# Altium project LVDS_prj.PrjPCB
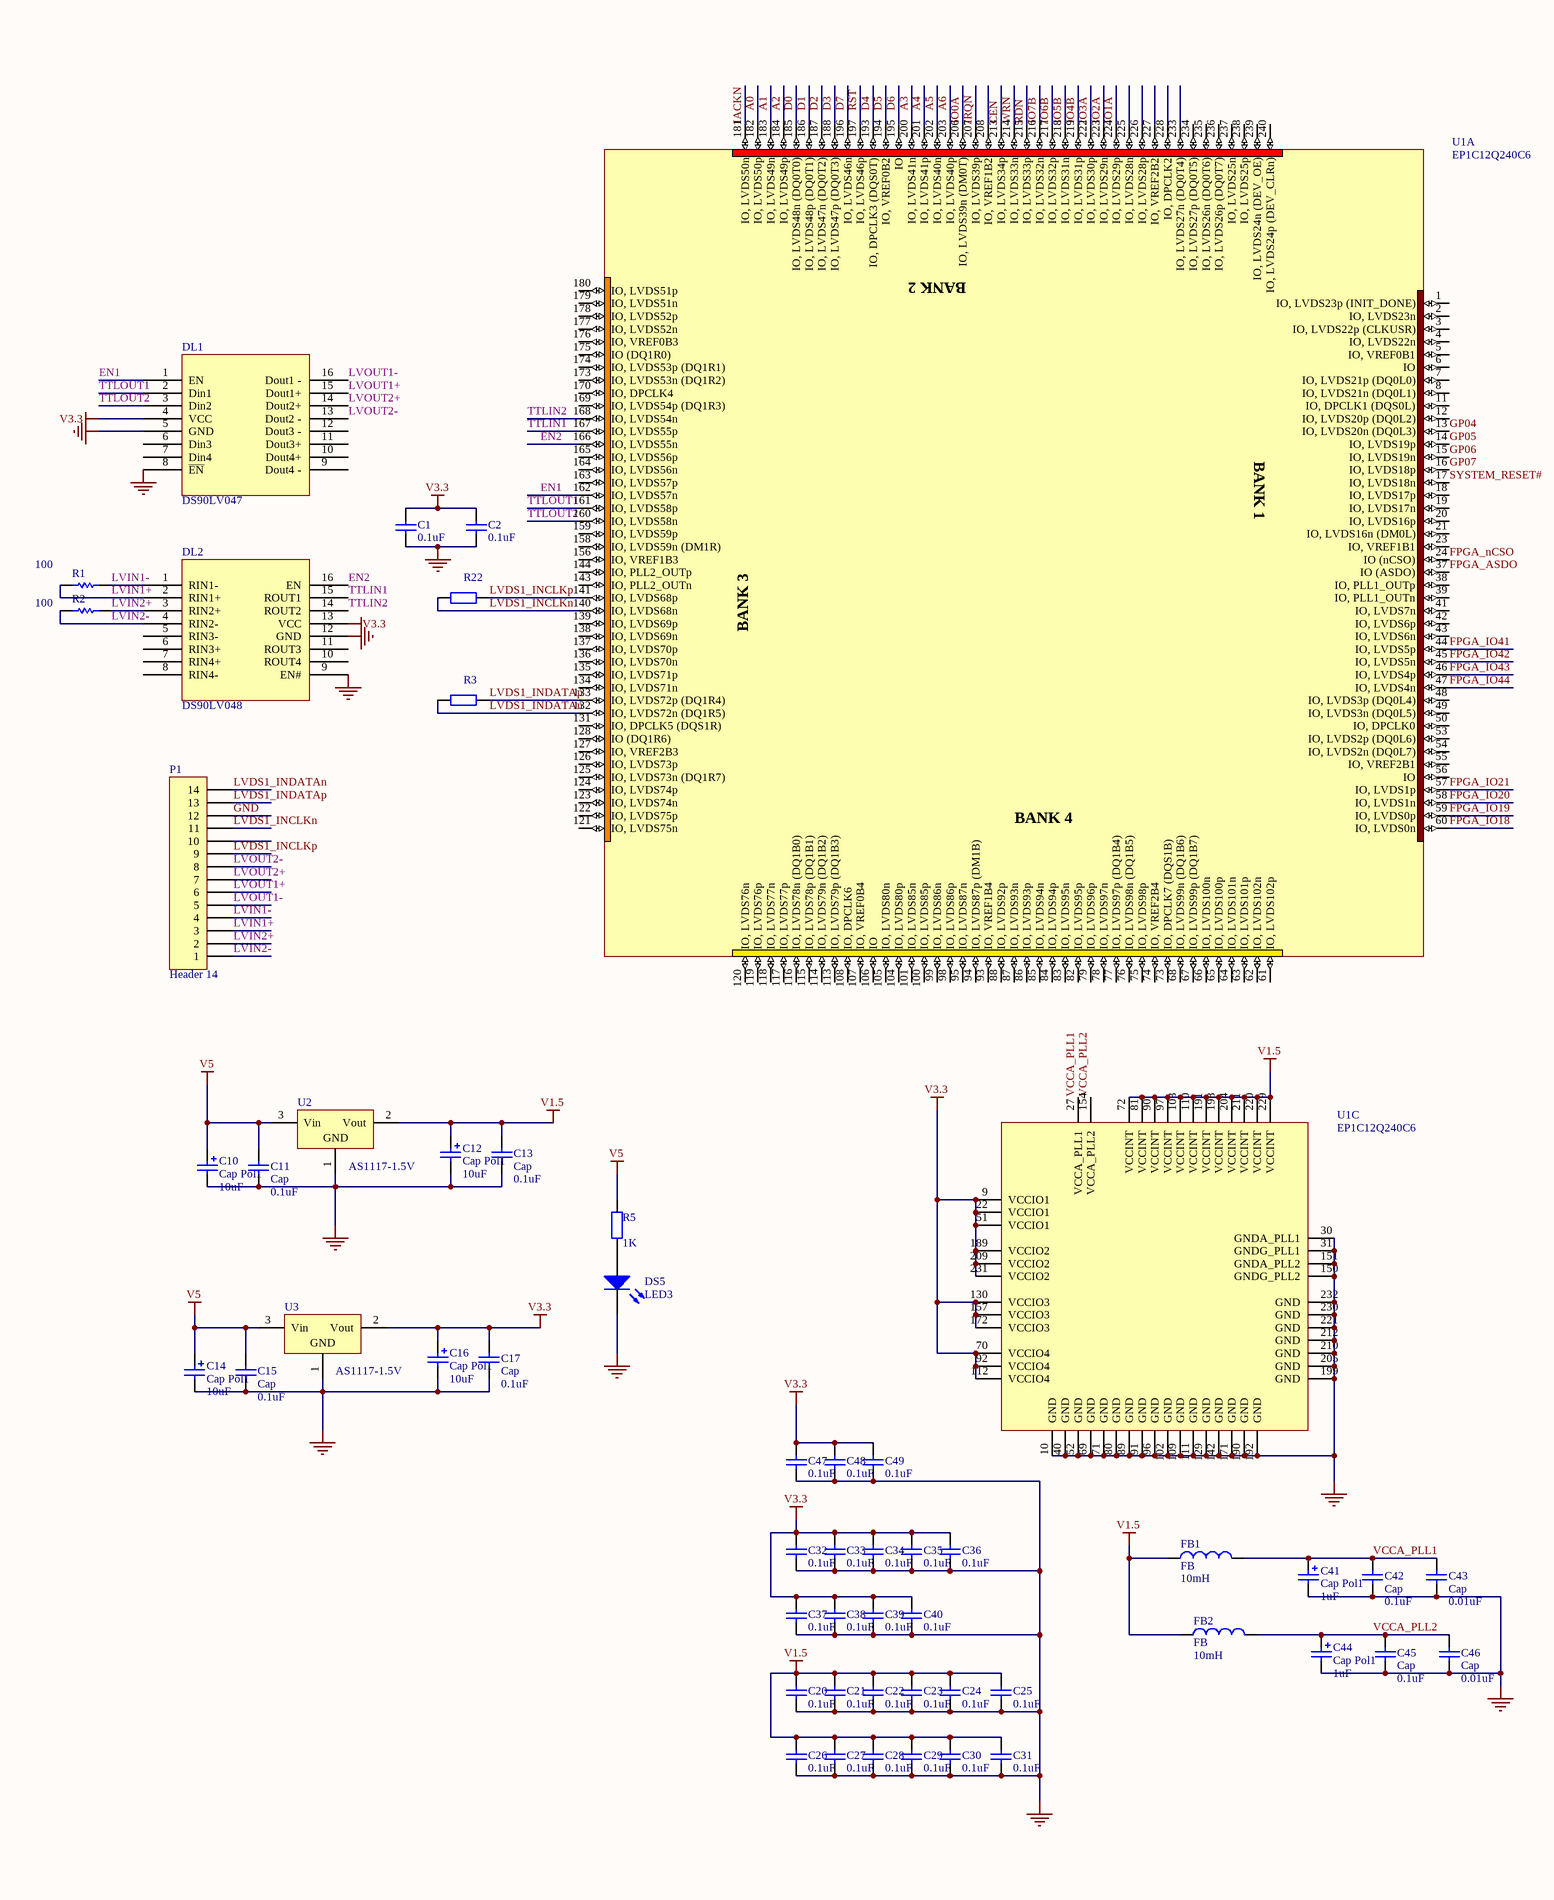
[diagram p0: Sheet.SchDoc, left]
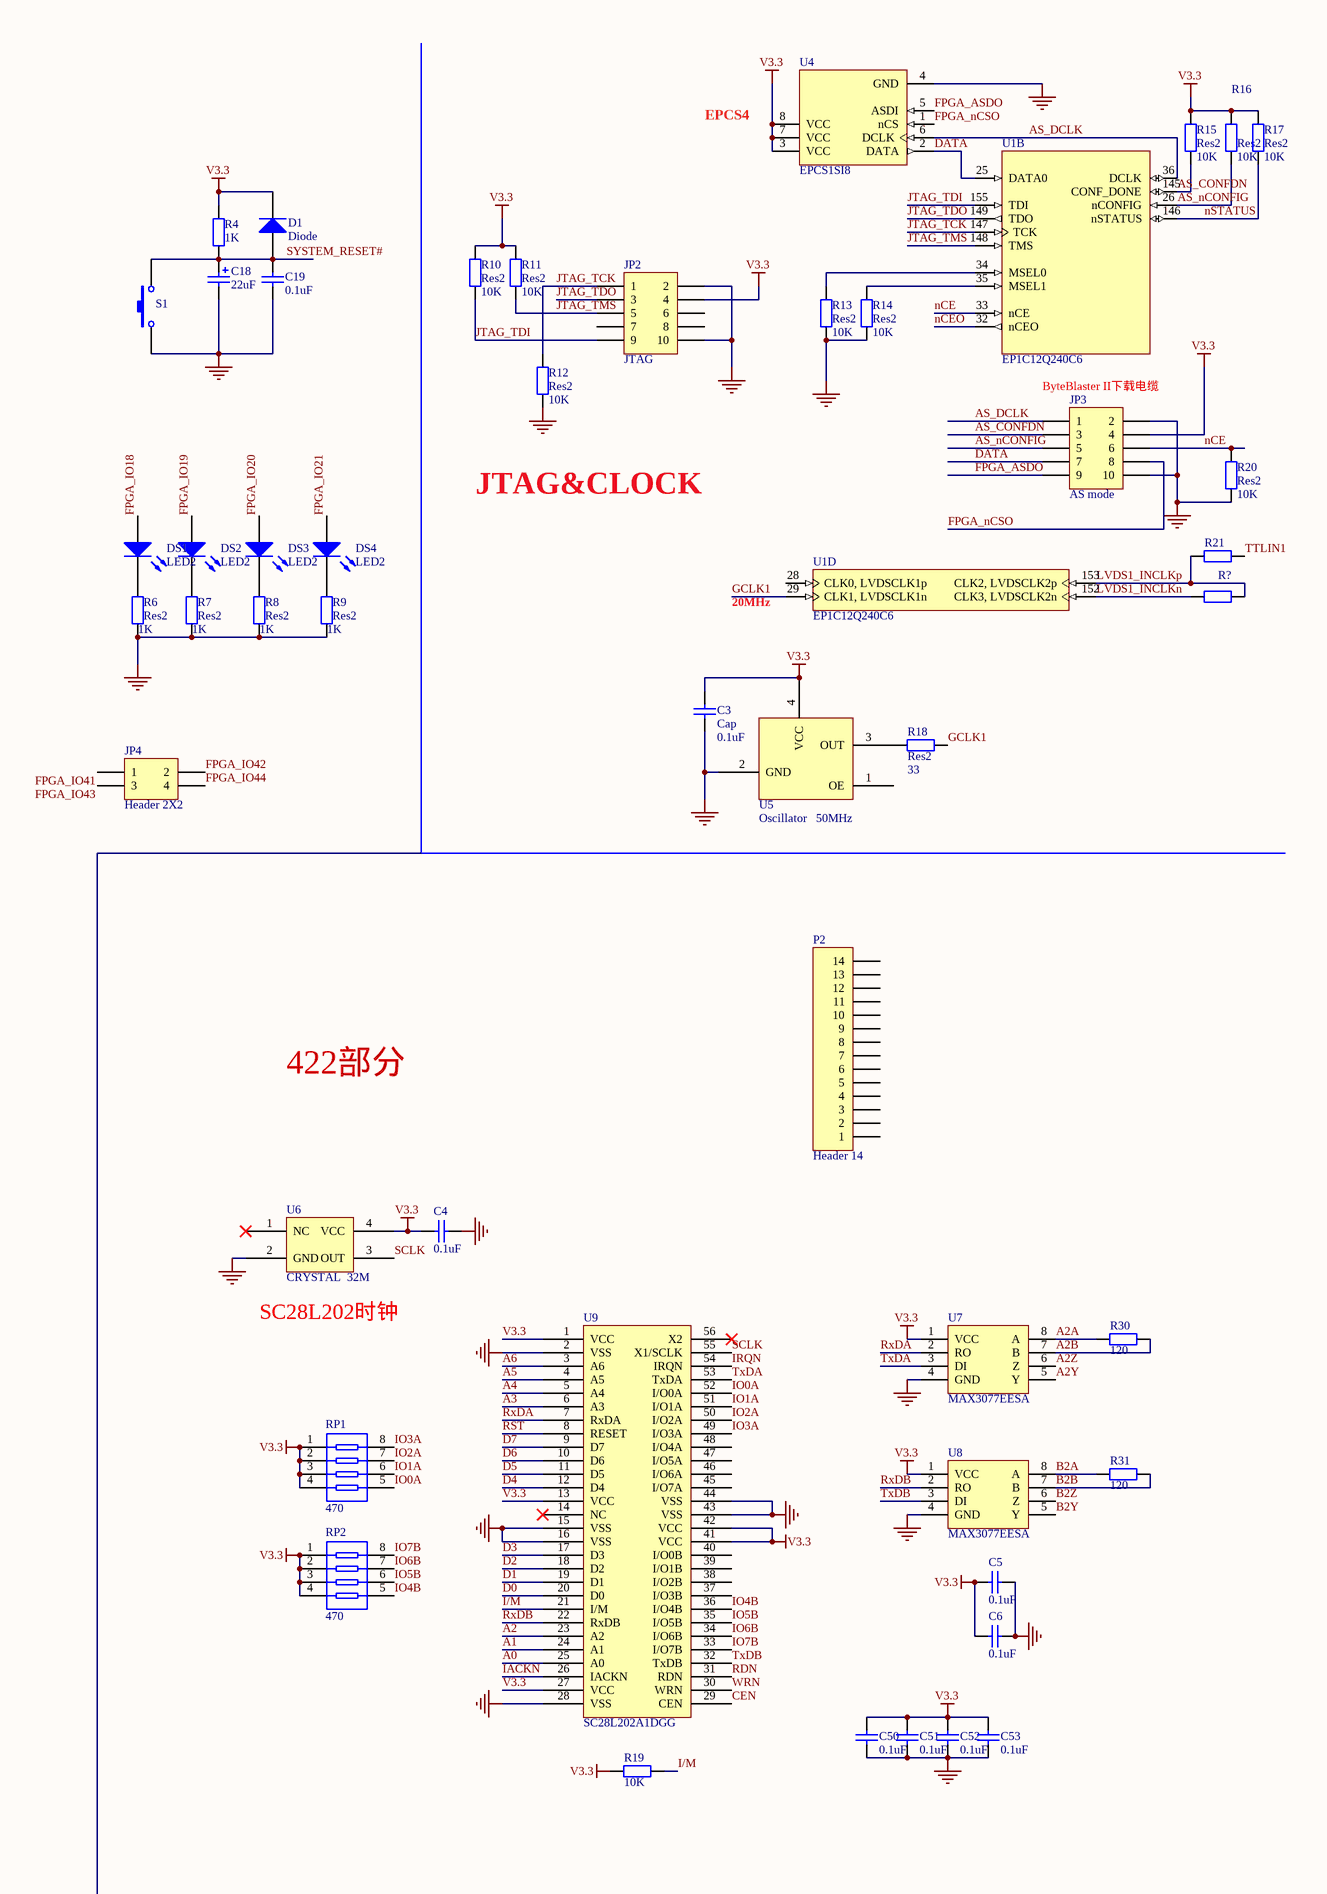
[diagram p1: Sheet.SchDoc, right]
1 sheet, 102 parts. Net scope: global (net labels, ports and power ports of the same name join across sheets).
Board files: PCB2_back_new.PcbDoc, LVDS_RS422.PcbDoc

## Sheet Sheet.SchDoc
size A2

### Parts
(Parts that share a designator on the sheet are numbered #1, #2 ... from top to bottom, then left to right.)
C1  0.1uF  [C1608-0603]
C2  0.1uF  [C1608-0603]
C3  Cap  value 0.1uF  [C1608-0603]
C4  0.1uF  [C1608-0603]
C5  0.1uF  [C1608-0603]
C6  0.1uF  [C1608-0603]
C10  Cap Pol1  value 10uF  [CC3216-1206]
C11  Cap  value 0.1uF  [C1608-0603]
C12  Cap Pol1  value 10uF  [CC3216-1206]
C13  Cap  value 0.1uF  [C1608-0603]
C14  Cap Pol1  value 10uF  [CC3216-1206]
C15  Cap  value 0.1uF  [C1608-0603]
C16  Cap Pol1  value 10uF  [CC3216-1206]
C17  Cap  value 0.1uF  [C1608-0603]
C18  22uF  [CC3216-1206]
C19  0.1uF  [C1608-0603]
C20  value 0.1uF  [0603]  (hidden comment: Cap)
C21  value 0.1uF  [0603]  (hidden comment: Cap)
C22  value 0.1uF  [0603]  (hidden comment: Cap)
C23  value 0.1uF  [0603]  (hidden comment: Cap)
C24  value 0.1uF  [0603]  (hidden comment: Cap)
C25  value 0.1uF  [0603]  (hidden comment: Cap)
C26  value 0.1uF  [0603]  (hidden comment: Cap)
C27  value 0.1uF  [0603]  (hidden comment: Cap)
C28  value 0.1uF  [0603]  (hidden comment: Cap)
C29  value 0.1uF  [0603]  (hidden comment: Cap)
C30  value 0.1uF  [0603]  (hidden comment: Cap)
C31  value 0.1uF  [0603]  (hidden comment: Cap)
C32  value 0.1uF  [0603]  (hidden comment: Cap)
C33  value 0.1uF  [0603]  (hidden comment: Cap)
C34  value 0.1uF  [0603]  (hidden comment: Cap)
C35  value 0.1uF  [0603]  (hidden comment: Cap)
C36  value 0.1uF  [0603]  (hidden comment: Cap)
C37  value 0.1uF  [0603]  (hidden comment: Cap)
C38  value 0.1uF  [0603]  (hidden comment: Cap)
C39  value 0.1uF  [0603]  (hidden comment: Cap)
C40  value 0.1uF  [0603]  (hidden comment: Cap)
C41  Cap Pol1  value 1uF  [C1608-0603]
C42  Cap  value 0.1uF  [C1608-0603]
C43  Cap  value 0.01uF  [C1608-0603]
C44  Cap Pol1  value 1uF  [C1608-0603]
C45  Cap  value 0.1uF  [C1608-0603]
C46  Cap  value 0.01uF  [C1608-0603]
C47  value 0.1uF  [0603]  (hidden comment: Cap)
C48  value 0.1uF  [0603]  (hidden comment: Cap)
C49  value 0.1uF  [0603]  (hidden comment: Cap)
C50  0.1uF  [C1608-0603]
C51  0.1uF  [C1608-0603]
C52  0.1uF  [C1608-0603]
C53  0.1uF  [C1608-0603]
D1  Diode  [SMD _LED]
DL1  DS90LV047  [SO-16]
DL2  DS90LV048  [SO-16]
DS1  LED2  [SMD _LED]
DS2  LED2  [SMD _LED]
DS3  LED2  [SMD _LED]
DS4  LED2  [SMD _LED]
DS5  LED3  [SMD _LED]
FB1  FB  value 10mH  [C1608-0603]
FB2  FB  value 10mH  [C1608-0603]
JP2  JTAG  [HDR2X5]
JP3  AS mode  [HDR2X5]
JP4  Header 2X2  [HDR2X2]
P1  Header 14  [CHAMP1.27-2H14A]
P2  Header 14  [CHAMP1.27-2H14A]
R1  value 100  [CR1608-0603]
R2  value 100  [CR1608-0603]
R3  Res2  [C1608-0603]  (value not drawn)
R4  1K  [CR1608-0603]
R5  value 1K  [CR1608-0603]  (hidden comment: Res2)
R6  Res2  value 1K  [C1608-0603]
R7  Res2  value 1K  [C1608-0603]
R8  Res2  value 1K  [C1608-0603]
R9  Res2  value 1K  [C1608-0603]
R10  Res2  value 10K  [C1608-0603]
R11  Res2  value 10K  [C1608-0603]
R12  Res2  value 10K  [C1608-0603]
R13  Res2  value 10K  [C1608-0603]
R14  Res2  value 10K  [C1608-0603]
R15  Res2  value 10K  [C1608-0603]
R16  Res2  value 10K  [C1608-0603]
R17  Res2  value 10K  [C1608-0603]
R18  Res2  value 33  [C1608-0603]
R19  10K  [CR1608-0603]
R20  Res2  value 10K  [C1608-0603]
R21  Res2  [C1608-0603]  (value not drawn)
R22#1  Res2  [C1608-0603]  (value not drawn)
R22#2  Res2  [C1608-0603]  (value not drawn)
R30  120  [CR1608-0603]
R31  120  [CR1608-0603]
RP1  470  [RP8]
RP2  470  [RP8]
S1  SW  [BUTTON]  (value not drawn)
U1  EP1C12Q240C6  [PQFP240]  (parts A,B,C,D of 4)
U2  AS1117-1.5V  [LM1117]
U3  AS1117-1.5V  [LM1117]
U4  EPCS1SI8  [SOIC8]
U5  Oscillator   50MHz  [OSC]
U6  CRYSTAL  32M  [OSC]
U7  MAX3077EESA  [SO-G8]
U8  MAX3077EESA  [SO-G8]
U9  SC28L202A1DGG  [TSSOP56]

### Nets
GND: C1.2 C2.2 C3.1 C4.2 C5.2 C6.2 C10.2 C11.1 C12.2 C13.1 C14.2 C15.1 C16.2 C17.1 C18.2 C19.1 C20.2 C21.2 C22.2 C23.2 C24.2 C25.2 C26.2 C27.2 C28.2 C29.2 C30.2 C31.2 C32.2 C33.2 C34.2 C35.2 C36.2 C37.2 C38.2 C39.2 C40.2 C41.2 C42.1 C43.1 C44.2 C45.1 C46.1 C47.2 C48.2 C49.2 C50.1 C51.1 C52.1 C53.1 DL1.5(GND) DL1.8(~{EN}) DL2.9(EN#) DL2.12(GND) DS5.2(K) JP2.2 JP2.10 JP3.2 JP3.10 P1.12 R6.2 R7.2 R8.2 R9.2 R12.1 R13.1 R14.1 R20.1 S1.1 U1.10(GND) U1.30(GNDA_PLL1) U1.31(GNDG_PLL1) U1.40(GND) U1.52(GND) U1.69(GND) U1.71(GND) U1.80(GND) U1.89(GND) U1.91(GND) U1.96(GND) U1.102(GND) U1.109(GND) U1.111(GND) U1.129(GND) U1.142(GND) U1.150(GNDG_PLL2) U1.151(GNDA_PLL2) U1.171(GND) U1.190(GND) U1.192(GND) U1.199(GND) U1.205(GND) U1.210(GND) U1.212(GND) U1.221(GND) U1.230(GND) U1.232(GND) U2.1(GND) U3.1(GND) U4.4(GND) U5.2(GND) U6.2(GND) U7.4(GND) U8.4(GND) U9.2(VSS) U9.15(VSS) U9.16(VSS) U9.28(VSS) U9.43(VSS) U9.44(VSS)
V1.5: C12.1 C13.2 C20.1 C21.1 C22.1 C23.1 C24.1 C25.1 C26.1 C27.1 C28.1 C29.1 C30.1 C31.1 FB1.1 FB2.1 U1.72(VCCINT) U1.81(VCCINT) U1.90(VCCINT) U1.97(VCCINT) U1.103(VCCINT) U1.110(VCCINT) U1.191(VCCINT) U1.198(VCCINT) U1.204(VCCINT) U1.211(VCCINT) U1.220(VCCINT) U1.229(VCCINT) U2.2(Vout)
V3.3: C1.1 C2.1 C3.2 C4.1 C5.1 C6.1 C16.1 C17.2 C32.1 C33.1 C34.1 C35.1 C36.1 C37.1 C38.1 C39.1 C40.1 C47.1 C48.1 C49.1 C50.2 C51.2 C52.2 C53.2 D1.2(K) DL1.4(VCC) DL2.13(VCC) JP2.4 JP3.4 R4.2 R10.2 R11.2 R15.2 R16.2 R17.2 R19.1 RP1.1 RP1.2 RP1.3 RP1.4 RP2.1 RP2.2 RP2.3 RP2.4 U1.9(VCCIO1) U1.22(VCCIO1) U1.51(VCCIO1) U1.70(VCCIO4) U1.92(VCCIO4) U1.112(VCCIO4) U1.130(VCCIO3) U1.157(VCCIO3) U1.172(VCCIO3) U1.189(VCCIO2) U1.209(VCCIO2) U1.231(VCCIO2) U3.2(Vout) U4.3(VCC) U4.7(VCC) U4.8(VCC) U5.4(VCC) U6.4(VCC) U7.1(VCC) U8.1(VCC) U9.1(VCC) U9.13(VCC) U9.27(VCC) U9.41(VCC) U9.42(VCC)
V5: C10.1 C11.2 C14.1 C15.2 R5.2 U2.3(Vin) U3.3(Vin)
A0: U1.182(IO,_LVDS50p) U9.25(A0)
A1: U1.183(IO,_LVDS49n) U9.24(A1)
A2: U1.184(IO,_LVDS49p) U9.23(A2)
A2A: R30.1 U7.8(A)
A2B: R30.2 U7.7(B)
A2Y: U7.5(Y)
A2Z: U7.6(Z)
A3: U1.200(IO,_LVDS41n) U9.6(A3)
A4: U1.201(IO,_LVDS41p) U9.5(A4)
A5: U1.202(IO,_LVDS40n) U9.4(A5)
A6: U1.203(IO,_LVDS40p) U9.3(A6)
AS_CONFDN: JP3.3 R15.1 U1.145(CONF_DONE)
AS_DCLK: JP3.1 U1.36(DCLK) U4.6(DCLK)
AS_nCONFIG: JP3.5 R16.1 U1.26(nCONFIG)
B2A: R31.1 U8.8(A)
B2B: R31.2 U8.7(B)
B2Y: U8.5(Y)
B2Z: U8.6(Z)
CEN: U1.213(IO,_LVDS34p) U9.29(CEN)
D0: U1.185(IO,_LVDS48n_(DQ0T0)) U9.20(D0)
D1: U1.186(IO,_LVDS48p_(DQ0T1)) U9.19(D1)
D2: U1.187(IO,_LVDS47n_(DQ0T2)) U9.18(D2)
D3: U1.188(IO,_LVDS47p_(DQ0T3)) U9.17(D3)
D4: U1.193(IO,_DPCLK3_(DQS0T)) U9.12(D4)
D5: U1.194(IO,_VREF0B2) U9.11(D5)
D6: U1.195(IO) U9.10(D6)
D7: U1.196(IO,_LVDS46n) U9.9(D7)
DATA: JP3.7 U1.25(DATA0) U4.2(DATA)
EN1: DL1.1(EN) U1.162(IO,_LVDS57n)
EN2: DL2.16(EN) U1.166(IO,_LVDS55n)
FPGA_ASDO: JP3.9 U1.37(IO_(ASDO)) U4.5(ASDI)
FPGA_IO18: DS1.1(A) U1.60(IO,_LVDS0n)
FPGA_IO19: DS2.1(A) U1.59(IO,_LVDS0p)
FPGA_IO20: DS3.1(A) U1.58(IO,_LVDS1n)
FPGA_IO21: DS4.1(A) U1.57(IO,_LVDS1p)
FPGA_IO41: JP4.1 U1.44(IO,_LVDS5p)
FPGA_IO42: JP4.2 U1.45(IO,_LVDS5n)
FPGA_IO43: JP4.3 U1.46(IO,_LVDS4p)
FPGA_IO44: JP4.4 U1.47(IO,_LVDS4n)
FPGA_nCSO: JP3.8 U1.24(IO_(nCSO)) U4.1(nCS)
GCLK1: R18.2 U1.29(CLK1,_LVDSCLK1n)
GP04: U1.13(IO,_LVDS20n_(DQ0L3))
GP05: U1.14(IO,_LVDS19p)
GP06: U1.15(IO,_LVDS19n)
GP07: U1.16(IO,_LVDS18p)
I/M: R19.2 U9.21(I/M)
IACKN: U1.181(IO,_LVDS50n) U9.26(IACKN)
IO0A: RP1.5 U1.206(IO,_LVDS39n_(DM0T)) U9.52(I/O0A)
IO1A: RP1.6 U1.224(IO,_LVDS29p) U9.51(I/O1A)
IO2A: RP1.7 U1.223(IO,_LVDS29n) U9.50(I/O2A)
IO3A: RP1.8 U1.222(IO,_LVDS30p) U9.49(I/O3A)
IO4B: RP2.5 U1.219(IO,_LVDS31p) U9.36(I/O4B)
IO5B: RP2.6 U1.218(IO,_LVDS31n) U9.35(I/O5B)
IO6B: RP2.7 U1.217(IO,_LVDS32p) U9.34(I/O6B)
IO7B: RP2.8 U1.216(IO,_LVDS32n) U9.33(I/O7B)
IRQN: U1.207(IO,_LVDS39p) U9.54(IRQN)
JTAG_TCK: JP2.1 R12.2 U1.147(TCK)
JTAG_TDI: JP2.9 R10.1 U1.155(TDI)
JTAG_TDO: JP2.3 U1.149(TDO)
JTAG_TMS: JP2.5 R11.1 U1.148(TMS)
LVDS1_INCLKn: P1.11 R22#1.1 R22#2.1 U1.140(IO,_LVDS68n) U1.152(CLK3,_LVDSCLK2n)
LVDS1_INCLKp: P1.9 R21.1 R22#1.2 R22#2.2 U1.141(IO,_LVDS68p) U1.153(CLK2,_LVDSCLK2p)
LVDS1_INDATAn: P1.14 R3.1 U1.132(IO,_LVDS72n_(DQ1R5))
LVDS1_INDATAp: P1.13 R3.2 U1.133(IO,_LVDS72p_(DQ1R4))
LVIN1+: DL2.2(RIN1+) P1.3 R1.2
LVIN1-: DL2.1(RIN1-) P1.4 R1.1
LVIN2+: DL2.3(RIN2+) P1.2 R2.1
LVIN2-: DL2.4(RIN2-) P1.1 R2.2
LVOUT1+: DL1.15(Dout1+) P1.6
LVOUT1-: DL1.16(Dout1_-) P1.5
LVOUT2+: DL1.14(Dout2+) P1.7
LVOUT2-: DL1.13(Dout2_-) P1.8
nCE: JP3.6 R20.2 U1.33(nCE)
nCEO: U1.32(nCEO)
nSTATUS: R17.1 U1.146(nSTATUS)
RDN: U1.215(IO,_LVDS33p) U9.31(RDN)
RST: U1.197(IO,_LVDS46p) U9.8(RESET)
RxDA: U7.2(RO) U9.7(RxDA)
RxDB: U8.2(RO) U9.22(RxDB)
SCLK: U6.3(OUT) U9.55(X1/SCLK)
SYSTEM_RESET#: C18.1 C19.2 D1.1(A) R4.1 S1.2 U1.17(IO,_LVDS18n)
TTLIN1: DL2.15(ROUT1) R21.2 U1.167(IO,_LVDS55p)
TTLIN2: DL2.14(ROUT2) U1.168(IO,_LVDS54n)
TTLOUT1: DL1.2(Din1) U1.161(IO,_LVDS58p)
TTLOUT2: DL1.3(Din2) U1.160(IO,_LVDS58n)
TxDA: U7.3(DI) U9.53(TxDA)
TxDB: U8.3(DI) U9.32(TxDB)
VCCA_PLL1: C41.1 C42.2 C43.2 FB1.2 U1.27(VCCA_PLL1)
VCCA_PLL2: C44.1 C45.2 C46.2 FB2.2 U1.154(VCCA_PLL2)
WRN: U1.214(IO,_LVDS33n) U9.30(WRN)
NetDS1_2: DS1.2(K) R6.1
NetDS2_2: DS2.2(K) R7.1
NetDS3_2: DS3.2(K) R8.1
NetDS4_2: DS4.2(K) R9.1
NetDS5_1: DS5.1(A) R5.1
NetR13_2: R13.2 U1.34(MSEL0)
NetR14_2: R14.2 U1.35(MSEL1)
NetR18_1: R18.1 U5.3(OUT)

Not connected (* = marked no-connect by the designer): DL1 6(Din3) 7(Din4) 9(Dout4_-) 10(Dout4+) 11(Dout3+) 12(Dout3_-); DL2 5(RIN3-) 6(RIN3+) 7(RIN4+) 8(RIN4-) 10(ROUT4) 11(ROUT3); JP2 6 7 8; P1 10; P2 1 2 3 4 5 6 7 8 9 10 11 12 13 14; U1 1(IO,_LVDS23p_(INIT_DONE)) 2(IO,_LVDS23n) 3(IO,_LVDS22p_(CLKUSR)) 4(IO,_LVDS22n) 5(IO,_VREF0B1) 6(IO) 7(IO,_LVDS21p_(DQ0L0)) 8(IO,_LVDS21n_(DQ0L1)) 11(IO,_DPCLK1_(DQS0L)) 12(IO,_LVDS20p_(DQ0L2)) 18(IO,_LVDS17p) 19(IO,_LVDS17n) 20(IO,_LVDS16p) 21(IO,_LVDS16n_(DM0L)) 23(IO,_VREF1B1) 28(CLK0,_LVDSCLK1p) 38(IO,_PLL1_OUTp) 39(IO,_PLL1_OUTn) 41(IO,_LVDS7n) 42(IO,_LVDS6p) 43(IO,_LVDS6n) 48(IO,_LVDS3p_(DQ0L4)) 49(IO,_LVDS3n_(DQ0L5)) 50(IO,_DPCLK0) 53(IO,_LVDS2p_(DQ0L6)) 54(IO,_LVDS2n_(DQ0L7)) 55(IO,_VREF2B1) 56(IO) 61(IO,_LVDS102p) 62(IO,_LVDS102n) 63(IO,_LVDS101p) 64(IO,_LVDS101n) 65(IO,_LVDS100p) 66(IO,_LVDS100n) 67(IO,_LVDS99p_(DQ1B7)) 68(IO,_LVDS99n_(DQ1B6)) 73(IO,_DPCLK7_(DQS1B)) 74(IO,_VREF2B4) 75(IO,_LVDS98p) 76(IO,_LVDS98n_(DQ1B5)) 77(IO,_LVDS97p_(DQ1B4)) 78(IO,_LVDS97n) 79(IO,_LVDS96p) 82(IO,_LVDS95p) 83(IO,_LVDS95n) 84(IO,_LVDS94p) 85(IO,_LVDS94n) 86(IO,_LVDS93p) 87(IO,_LVDS93n) 88(IO,_LVDS92p) 93(IO,_VREF1B4) 94(IO,_LVDS87p_(DM1B)) 95(IO,_LVDS87n) 98(IO,_LVDS86p) 99(IO,_LVDS86n) 100(IO,_LVDS85p) 101(IO,_LVDS85n) 104(IO,_LVDS80p) 105(IO,_LVDS80n) 106(IO) 107(IO,_VREF0B4) 108(IO,_DPCLK6) 113(IO,_LVDS79p_(DQ1B3)) 114(IO,_LVDS79n_(DQ1B2)) 115(IO,_LVDS78p_(DQ1B1)) 116(IO,_LVDS78n_(DQ1B0)) 117(IO,_LVDS77p) 118(IO,_LVDS77n) 119(IO,_LVDS76p) 120(IO,_LVDS76n) 121(IO,_LVDS75n) 122(IO,_LVDS75p) 123(IO,_LVDS74n) 124(IO,_LVDS74p) 125(IO,_LVDS73n_(DQ1R7)) 126(IO,_LVDS73p) 127(IO,_VREF2B3) 128(IO_(DQ1R6)) 131(IO,_DPCLK5_(DQS1R)) 134(IO,_LVDS71n) 135(IO,_LVDS71p) 136(IO,_LVDS70n) 137(IO,_LVDS70p) 138(IO,_LVDS69n) 139(IO,_LVDS69p) 143(IO,_PLL2_OUTn) 144(IO,_PLL2_OUTp) 156(IO,_VREF1B3) 158(IO,_LVDS59n_(DM1R)) 159(IO,_LVDS59p) 163(IO,_LVDS57p) 164(IO,_LVDS56n) 165(IO,_LVDS56p) 169(IO,_LVDS54p_(DQ1R3)) 170(IO,_DPCLK4) 173(IO,_LVDS53n_(DQ1R2)) 174(IO,_LVDS53p_(DQ1R1)) 175(IO_(DQ1R0)) 176(IO,_VREF0B3) 177(IO,_LVDS52n) 178(IO,_LVDS52p) 179(IO,_LVDS51n) 180(IO,_LVDS51p) 208(IO,_VREF1B2) 225(IO,_LVDS28n) 226(IO,_LVDS28p) 227(IO,_VREF2B2) 228(IO,_DPCLK2) 233(IO,_LVDS27n_(DQ0T4)) 234(IO,_LVDS27p_(DQ0T5)) 235(IO,_LVDS26n_(DQ0T6)) 236(IO,_LVDS26p_(DQ0T7)) 237(IO,_LVDS25n) 238(IO,_LVDS25p) 239(IO,_LVDS24n_(DEV_OE)) 240(IO,_LVDS24p_(DEV_CLRn)); U5 1(OE); U6 1(NC)*; U9 14(NC)* 37(I/O3B) 38(I/O2B) 39(I/O1B) 40(I/O0B) 45(I/O7A) 46(I/O6A) 47(I/O5A) 48(I/O4A) 56(X2)*

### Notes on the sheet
- EPCS4
- (near JP3) ByteBlaster II下载电缆
- JTAG&CLOCK
- (near U1) 20MHz
- 422部分
- (near U6) SC28L202时钟

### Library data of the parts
C1 C2 = Cap: Capacitor; Manufacturer: Generic Components; Class: Passive; Value: 100pF
C3 C11 C13 C15 C17 C20-C40 C42 C43 C45-C49 = Cap: Capacitor
C4-C6 C19 C50-C53 = Cap: Capacitor; Manufacturer: Generic Components; Value: 100pF; Class: Passive
C10 C12 C14 C16 C41 C44 = Cap Pol1: Polarized Capacitor (Radial)
C18 = Cap Pol3: Polarized Capacitor (Surface Mount); Manufacturer: Generic Components; Class: Passive; Value: 10uF
D1 = Diode: Default Diode; Manufacturer: Generic Components; Class: Discrete; SubClass: Diode - Switching
DS1-DS4 = LED2: Typical RED, GREEN, YELLOW, AMBER GaAs LED
DS5 = LED3: Typical BLUE SiC LED; Revision 1: Jul-2002: Re-released for DXP Platform.; Revision 2: 17-Dec-2003: PCB Footprint replaced.
FB1 FB2 = Inductor
JP2 JP3 = Header 5X2: Header, 5-Pin, Dual row
JP4 = Header 2X2: Header, 2-Pin, Dual row
P1 P2 = Header 14: Header, 14-Pin
R1 R2 = Res1: Resistor; Manufacturer: Generic Components; Class: Passive
R3 R21 R22#1 R22#2 = Res2: Resistor; Value: 100 1%
R4 R19 = Res2: Resistor; Value: 120
R5-R18 R20 R30 R31 = Res2: Resistor
RP1 RP2 = RESPACK8
S1 = SW: Switch; Manufacturer: Generic Components
U1 = EP1C12Q240C6: Cyclone Family, 1.5V FPGA, 173 I/O Pins, 2 x PLLs, Commercial Grade, Speed Grade 6; Package Information: Latest Revision: ver11.0, Feb-2003; Code - JEDEC: MS-029-GA
U2 U3 = Volt Reg: Voltage Regulator; Code - JEDEC: SMD-220
U4 = EPCS1SI8: EPCS1 Series, In-system programmable 3.3V configuration device, 8-Pin SOIC, 1-Megabit, Industrial Grade; Package Information: Latest Revision: ver11.0, Feb-2003; Serially configures: Cyclone FPGAs; Code - JEDEC: MS-012-AA; Code - IPC: SO8
U5 = Oscillator
U6 = CRYSTAL4
U7 U8 = MAX3077E
U9 = SC28L202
